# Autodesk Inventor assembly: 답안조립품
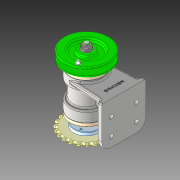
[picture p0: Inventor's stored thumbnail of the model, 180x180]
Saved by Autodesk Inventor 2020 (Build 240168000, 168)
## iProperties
Created: 2024-02
Part Number: 답안조립품
Document SubType Name: Assembly
Designer: oem
Author: oem
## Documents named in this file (18)
- C:\Users\oem\Desktop\740204V1002\답안조립품.iam
- C:\Users\oem\Desktop\740204V1002\V-벨트풀리.ipt
- C:\Users\oem\Desktop\740204V1002\가스켓.ipt
- C:\Users\oem\Desktop\740204V1002\깊은 홈 볼 베어링 6204.ipt
- C:\Users\oem\Desktop\740204V1002\본체.ipt
- C:\Users\oem\Desktop\740204V1002\스프로킷.ipt
- C:\Users\oem\Desktop\740204V1002\스프링 와셔 M5.ipt
- C:\Users\oem\Desktop\740204V1002\스프링 와셔 M10.ipt
- C:\Users\oem\Desktop\740204V1002\앤드 캡.ipt
- C:\Users\oem\Desktop\740204V1002\오일 실 20 32 5.ipt
- C:\Users\oem\Desktop\740204V1002\육각 너트 M10x1.ipt
- C:\Users\oem\Desktop\740204V1002\육각 소켓 머리 볼트 M4 x 10.ipt
- C:\Users\oem\Desktop\740204V1002\육각 소켓 머리 볼트 M5 x 12.ipt
- C:\Users\oem\Desktop\740204V1002\축.ipt
- C:\Users\oem\Desktop\740204V1002\커버.ipt
- C:\Users\oem\Desktop\740204V1002\평와셔 M10.ipt
- C:\Users\oem\Desktop\740204V1002\평행 키 5x5x12.ipt
- C:\Users\oem\Desktop\740204V1002\플랜지.ipt
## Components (4 placed, 3 different names)
1. V-벨트풀리:1
2. 가스켓:1
3. 플랜지:1
4. 가스켓:2
